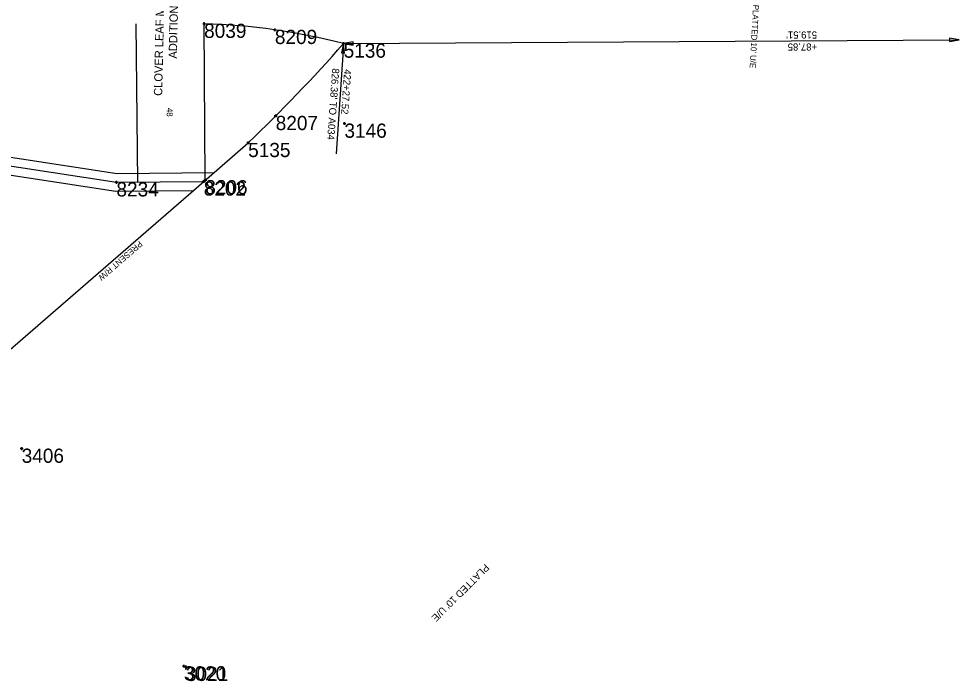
# Model space of a CAD drawing. Extents: x 2145146 to 2158053, y 137507 to 150829.
# Drawn here: x 2150026 to 2150819, y 143365 to 143925 of the extents above; entities that cross this region are included whole.
import ezdxf

# ---------------------------------------------------------------- set-up
doc = ezdxf.new("R2010")
doc.units = 0
for name, color, linetype in [('ALIGN_Cogo Points', 7, 'Continuous'), ('ALIGN_ROW Dimension', 7, 'Continuous'), ('ALIGN_ROW Line', 7, 'Continuous'), ('ALIGN_ROW Text', 7, 'Continuous'), ('PLSS_Easement', 7, 'Continuous'), ('PLSS_Lot Line', 7, 'Continuous'), ('PLSS_Property Line', 7, 'Continuous'), ('PLSS_Text', 7, 'Continuous'), ('PLSS_Text_TURNED OFF', 7, 'Continuous')]:
    doc.layers.add(name, color=color, linetype=linetype)

# ---------------------------------------------------------------- blocks, each defined once
blk = doc.blocks.new('Arrowhd')
at = {"layer": 'PLSS_Property Line'}
blk.add_lwpolyline([(0.125, -0.021), (0.125, 0.021), (0, 0)], close=True, dxfattribs=at)

msp = doc.modelspace()

# ---------------------------------------------------------------- linework, layer by layer
at = {"layer": 'ALIGN_Cogo Points'}
for points in [[(2150181.95, 143920.65), (2150181.95, 143921.85), (2150181.95, 143920.65), (2150180.75, 143920.65), (2150181.95, 143920.65), (2150181.95, 143919.45), (2150181.95, 143920.65), (2150183.15, 143920.65)], [(2150241.68, 143915.47), (2150241.68, 143916.67), (2150241.68, 143915.47), (2150240.48, 143915.47), (2150241.68, 143915.47), (2150241.68, 143914.27), (2150241.68, 143915.47), (2150242.88, 143915.47)], [(2150299.7, 143903.93), (2150299.7, 143905.13), (2150299.7, 143903.93), (2150298.5, 143903.93), (2150299.7, 143903.93), (2150299.7, 143902.73), (2150299.7, 143903.93), (2150300.9, 143903.93)], [(2150242.36, 143842.79), (2150242.36, 143843.99), (2150242.36, 143842.79), (2150241.16, 143842.79), (2150242.36, 143842.79), (2150242.36, 143841.59), (2150242.36, 143842.79), (2150243.56, 143842.79)], [(2150300.37, 143836.3), (2150300.37, 143837.5), (2150300.37, 143836.3), (2150299.17, 143836.3), (2150300.37, 143836.3), (2150300.37, 143835.1), (2150300.37, 143836.3), (2150301.57, 143836.3)], [(2150219.11, 143819.98), (2150219.11, 143821.18), (2150219.11, 143819.98), (2150217.91, 143819.98), (2150219.11, 143819.98), (2150219.11, 143818.78), (2150219.11, 143819.98), (2150220.31, 143819.98)], [(2150107.94, 143786.72), (2150107.94, 143787.92), (2150107.94, 143786.72), (2150106.74, 143786.72), (2150107.94, 143786.72), (2150107.94, 143785.52), (2150107.94, 143786.72), (2150109.14, 143786.72)], [(2150181.61, 143787.42), (2150181.61, 143788.62), (2150181.61, 143787.42), (2150180.41, 143787.42), (2150181.61, 143787.42), (2150181.61, 143786.22), (2150181.61, 143787.42), (2150182.81, 143787.42)], [(2150182.9, 143788.54), (2150182.9, 143789.74), (2150182.9, 143788.54), (2150181.7, 143788.54), (2150182.9, 143788.54), (2150182.9, 143787.34), (2150182.9, 143788.54), (2150184.1, 143788.54)], [(2150027.96, 143561.75), (2150027.96, 143562.95), (2150027.96, 143561.75), (2150026.76, 143561.75), (2150027.96, 143561.75), (2150027.96, 143560.55), (2150027.96, 143561.75), (2150029.16, 143561.75)], [(2150164.92, 143377.96), (2150164.92, 143379.16), (2150164.92, 143377.96), (2150163.72, 143377.96), (2150164.92, 143377.96), (2150164.92, 143376.76), (2150164.92, 143377.96), (2150166.12, 143377.96)], [(2150166.55, 143377.48), (2150166.55, 143378.68), (2150166.55, 143377.48), (2150165.35, 143377.48), (2150166.55, 143377.48), (2150166.55, 143376.28), (2150166.55, 143377.48), (2150167.75, 143377.48)]]:
    msp.add_lwpolyline(points, dxfattribs=at)
at = {"layer": 'ALIGN_ROW Dimension'}
for points in [[(2150299.7, 143902.73), (2150293.5, 143810.79)], [(2150299.59, 143903.95), (2150819.21, 143907.08)]]:
    msp.add_lwpolyline(points, dxfattribs=at)
at = {"layer": 'ALIGN_ROW Line'}
msp.add_lwpolyline([(2149868.04, 143567.55), (2149863.36, 143587.06), (2149988.5, 143619.76), (2150172.87, 143779.84), (2150219.11, 143819.98)], dxfattribs=at)
for centre, radius, start, end in [((2150164.92, 143377.96), 542.96, 75.62649, 88.20218), ((2149252.26, 144828.89), 1397.39, 313.7809, 318.55346)]:
    msp.add_arc(centre, radius, start, end, dxfattribs=at)
at = {"layer": 'PLSS_Easement'}
for points in [[(2149823.78, 143837.79), (2150108.48, 143794.23), (2150190.34, 143795)], [(2149827.56, 143822.04), (2150107.41, 143779.22), (2150172.87, 143779.84)]]:
    msp.add_lwpolyline(points, dxfattribs=at)
at = {"layer": 'PLSS_Lot Line'}
for points in [[(2150125.93, 143786.89), (2150124.67, 143920.56)], [(2150182.9, 143788.54), (2150181.95, 143920.65)], [(2149804.32, 143833.18), (2150107.94, 143786.72), (2150181.61, 143787.42)]]:
    msp.add_lwpolyline(points, dxfattribs=at)

# ---------------------------------------------------------------- block references
at = {"layer": 'ALIGN_ROW Dimension'}
for p, xscale, yscale, rotation in [((2150299.7, 143903.97), 64.99999999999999, 65.00000000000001, -93.8366707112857), ((2150299.59, 143903.95), 64.99999999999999, 65, 0.34425883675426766), ((2150819.21, 143907.08), 65.00000000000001, 64.99999999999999, -179.65177652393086)]:
    msp.add_blockref('Arrowhd', p, dxfattribs=dict(at, xscale=xscale, yscale=yscale, rotation=rotation))

# ---------------------------------------------------------------- texts
at = {"layer": 'ALIGN_Cogo Points'}
for s, p in [('8039', (2150181.95, 143908.65)), ('8209', (2150241.68, 143903.47)), ('5136', (2150299.7, 143891.93)), ('8207', (2150242.36, 143830.79)), ('3146', (2150300.37, 143824.3)), ('5135', (2150219.11, 143807.98)), ('8234', (2150107.94, 143774.72)), ('8202', (2150181.61, 143775.42)), ('8206', (2150182.9, 143776.54)), ('3406', (2150027.96, 143549.75)), ('3020', (2150164.92, 143365.96)), ('3021', (2150166.55, 143365.48))]:
    msp.add_text(s, height=12, dxfattribs=at).set_placement(p)
at = {"layer": 'ALIGN_ROW Dimension'}
for s, rotation, p in [("519.51'", 180, (2150699.23, 143914.11)), ('+87.85', 180, (2150699.23, 143903.95)), ("826.38' TO A034", 265.91144, (2150290.1, 143883.06)), ('422+27.52', 265.91144, (2150300.24, 143882.34))]:
    msp.add_text(s, height=6, rotation=rotation, dxfattribs=at).set_placement(p)
at = {"layer": 'ALIGN_ROW Text'}
msp.add_text('PRESENT R/W', height=5, rotation=220.94063, dxfattribs=at).set_placement((2150127.22, 143737.51))
at = {"layer": 'PLSS_Text'}
for s, height, rotation, p in [("PLATTED 10' U/E", 5, 266.86433, (2150645.3, 143936.78)), ('48', 5, 270, (2150150.42, 143849.56)), ("PLATTED 10' U/E", 6, 224.78033, (2150419.03, 143464.69))]:
    msp.add_text(s, height=height, rotation=rotation, dxfattribs=at).set_placement(p)
at = {"layer": 'PLSS_Text_TURNED OFF'}
for s, p in [('CLOVER LEAF MANOR', (2150146.5, 143859.63)), ('ADDITION', (2150158.92, 143891.12))]:
    msp.add_text(s, height=7, rotation=88.67232, dxfattribs=at).set_placement(p)

doc.saveas('drawing.dxf')
